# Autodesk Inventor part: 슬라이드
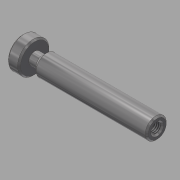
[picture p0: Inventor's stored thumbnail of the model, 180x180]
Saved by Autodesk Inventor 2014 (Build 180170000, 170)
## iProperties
Created: 2015-12
Part Number: 슬라이드
Document SubType Name: Modeling
Designer: mdu
Density: 8.08 g/cm^3
Material: 스테인리스강
Appearance: 반광택
Mass: 114.493 g
Surface Area: 49.8963 cm^2
Volume: 14.17 cm^3
Author: mdu
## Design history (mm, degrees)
sketch "스케치1"
  geometry: L1 (-45, 0)-(45, 0); L2 (-45, 0)-(-45, 10.5); L3 (-45, 10.5)-(-37, 10.5); L4 (-37, 10.5)-(-37, 4); L5 (-37, 4)-(-32, 4); L6 (-32, 4)-(-29, 7); L7 (-29, 7)-(45, 7); L8 (45, 7)-(45, 0); 2 further points
  constraints: 16 end point, 4 parallel, 2 perpendicular, 1 coincident, 1 horizontal, 1 midpoint
  dimensions: "d0" = 90 distance of L1.start L1.end; "d1" = 21 diameter of L3 L1; "d2" = 14 diameter of L7 L1; "d3" = 8 diameter of L5 L1; "d4" = 8 distance of L2.end L3.end; "d5" = 5 distance of L4.end L5.end; "d6" = 135 deg angle of L6 L5
revolve "회전1" sketch "스케치1" stored, may be unused: angle "d7" = 90 deg
chamfer "모따기1" distance "d8" = 1; stored, may be unused: second distance "d9" = 2, angle "d10" = 45 deg
hole "구멍1" diameter "d13" = 6.647; stored, may be unused: countersink angle "d17" = 90 deg, drill point angle "d19" = 118 deg; dims "d11" = 10, "d12" = 10, "d14" = 9, "d15" = 4, "d16" = 2, "d18" = 12
chamfer "모따기2" distance "d20" = 1; stored, may be unused: second distance "d21" = 2, angle "d22" = 45 deg
node "솔리드1"
